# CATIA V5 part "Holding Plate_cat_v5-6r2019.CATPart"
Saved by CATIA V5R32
Part number: Holding Plate
Bounding box of the stored display mesh (mm): x -16 to 16, y -16 to 16, z 0 to 7
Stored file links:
  D:\PROJECTS\Project 2022\CATIA V5 6R 2022\Resources\Tutorial Files\c13_catia_v5_6r2022_tut\c13tut2\Bench vice\Holding Plate_cat_v5-6r2019.CATPart
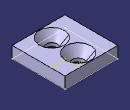
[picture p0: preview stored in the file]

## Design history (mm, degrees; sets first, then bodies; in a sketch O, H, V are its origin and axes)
Body1 (main body)
  Sketch1 on xy-plane, origin (0, 0, 0), H (1, 0, 0), V (0, 1, 0)
    line L1 (-16, 16) -> (16, 16)
    line L2 (16, 16) -> (16, -16)
    line L3 (16, -16) -> (-16, -16)
    line L4 (-16, -16) -> (-16, 16)
    construction line L5 (-16, 16) -> (16, -16)
    length L2 = 32
    length L3 = 32
    distance H L3 = 16
    distance V L4 = 16
    horizontal: L1 H, L3 H
    vertical: L2 V, L4 V
  Pad1: profile Sketch1, direction (0, 0, 1), length 7
  Sketch2 on face of Pad1, origin (-0.9262, 8.6399, 7), H (1, 0, 0), V (0, 1, 0)
    point P1 (0.9262, -0.6399)
    reference intersected line E1 through (0.9262, 0) direction (0, 1) from yz-plane
    reference projected line E3 (-15.0738, 7.3601) -> (16.9262, 7.3601) from edge of Pad1
    distance P1 E3 = 8
    coincidence: E1 P1
  Hole1: placed by Sketch2, at (0, 8, 7) direction (0, 0, -1), diameter 7, depth 10, countersink depth 5, countersink angle 80
  Mirror1: of Hole1, about zx-plane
